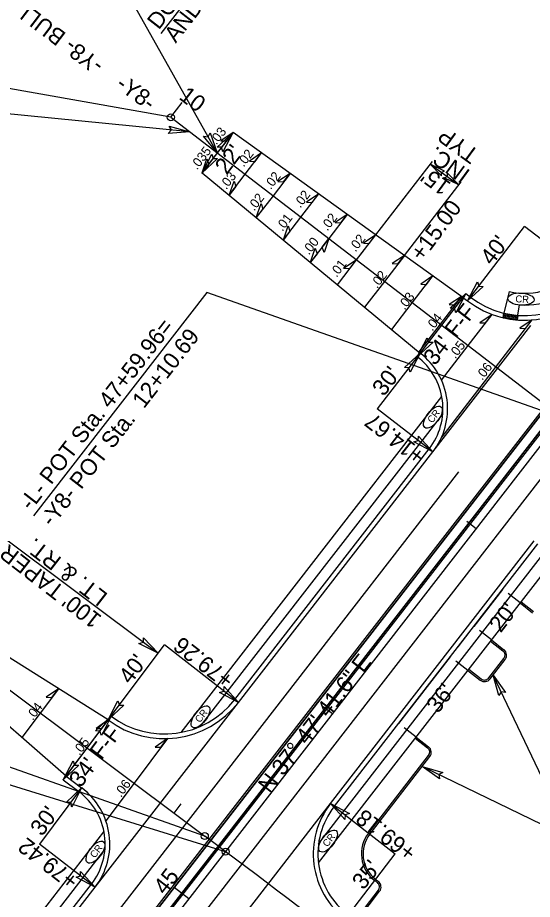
# Model space of a CAD drawing. Extents: x 2010838 to 2015151, y 441905 to 447792.
# Drawn here: x 2014378.8 to 2014598.5, y 445680 to 446056.5 of the extents above; entities that cross this region are included whole.
import ezdxf

# ---------------------------------------------------------------- set-up
doc = ezdxf.new("R2010")
doc.units = 0
for name, color, linetype in [('A-Wall-Blow', 7, 'Continuous'), ('A-Wall-Comp', 7, 'Continuous'), ('B-Border', 7, 'Continuous'), ('B-Sheet Number', 7, 'Continuous'), ('C-Building', 7, 'Continuous'), ('C-CURB STOPS', 7, 'Continuous'), ('C-EOP 1', 7, 'Continuous'), ('C-Grave Plots', 7, 'Continuous'), ('CLRD', 7, 'Continuous'), ('Cont-2-Lidar', 7, 'Continuous'), ('Default_10ft_LIDAR_Contou', 7, 'Continuous'), ('Default_2FT_LIDAR_Contour', 7, 'Continuous'), ('HATCH', 7, 'Continuous'), ('s-Existing Major', 7, 'Continuous'), ('S-Existing Minor', 7, 'Continuous'), ('S-overhead electric', 7, 'Continuous'), ('S-SITE LIGHT POLE REMOVE', 7, 'Continuous'), ('TEXT-LG', 7, 'Continuous'), ('TEXT-MED', 7, 'Continuous'), ('X2', 7, 'Continuous'), ('X4', 7, 'Continuous')]:
    doc.layers.add(name, color=color, linetype=linetype)

msp = doc.modelspace()

# ---------------------------------------------------------------- linework, layer by layer
at = {"layer": 'A-Wall-Blow'}
for p, q in [((2014470.79, 446007.47), (2014464.14, 445998.82)), ((2014464.19, 445998.88), (2014457.57, 445990.26)), ((2014475.94, 445989.56), (2014482.98, 445998.72)), ((2014469.13, 445980.69), (2014475.94, 445989.56)), ((2014495.17, 445989.96), (2014487.84, 445980.42)), ((2014499.73, 445971.28), (2014507.36, 445981.21)), ((2014487.84, 445980.42), (2014480.7, 445971.13)), ((2014492.26, 445961.56), (2014499.73, 445971.28)), ((2014519.56, 445972.46), (2014511.63, 445962.14)), ((2014511.63, 445962.14), (2014503.82, 445951.99)), ((2014523.52, 445953), (2014531.75, 445963.71)), ((2014543.94, 445954.96), (2014535.41, 445943.86)), ((2014515.39, 445942.42), (2014523.52, 445953)), ((2014535.41, 445943.86), (2014526.95, 445932.85)), ((2014547.31, 445934.72), (2014556.13, 445946.21)), ((2014568.33, 445937.46), (2014559.2, 445925.58)), ((2014538.51, 445923.28), (2014547.31, 445934.72)), ((2014571.1, 445916.44), (2014581.32, 445929.75)), ((2014559.2, 445925.58), (2014550.08, 445913.71)), ((2014559.6, 445876.86), (2014598.42, 445927.38)), ((2014559.76, 445901.69), (2014571.1, 445916.44)), ((2014396.27, 445769.9), (2014388.51, 445759.53)), ((2014388.51, 445759.53), (2014380.65, 445749.03)), ((2014408.53, 445744.55), (2014417.52, 445756.56)), ((2014442.78, 445748.6), (2014428.54, 445729.57)), ((2014399.54, 445732.54), (2014408.52, 445744.55)), ((2014428.54, 445729.57), (2014416.51, 445713.49))]:
    msp.add_line(p, q, dxfattribs=at)
at = {"layer": 'A-Wall-Comp'}
for points in [[(2014470.79, 446007.47), (2014465.55, 446003.93), (2014467.97, 446003.8)], [(2014457.57, 445990.26), (2014459.64, 445996.24), (2014460.39, 445993.93)], [(2014482.98, 445998.72), (2014477.74, 445995.18), (2014480.16, 445995.05)], [(2014495.17, 445989.96), (2014489.93, 445986.43), (2014492.35, 445986.3)], [(2014469.13, 445980.69), (2014471.2, 445986.67), (2014471.95, 445984.36)], [(2014507.36, 445981.21), (2014502.12, 445977.67), (2014504.55, 445977.55)], [(2014480.7, 445971.13), (2014482.77, 445977.1), (2014483.51, 445974.79)], [(2014519.56, 445972.46), (2014514.32, 445968.92), (2014516.74, 445968.79)], [(2014492.26, 445961.56), (2014494.33, 445967.53), (2014495.08, 445965.22)], [(2014511.63, 445962.14), (2014509.61, 445956.15), (2014508.84, 445958.45)], [(2014531.75, 445963.71), (2014526.51, 445960.17), (2014528.93, 445960.04)], [(2014503.82, 445951.99), (2014505.89, 445957.96), (2014506.64, 445955.65)], [(2014543.94, 445954.96), (2014538.7, 445951.42), (2014541.12, 445951.29)], [(2014523.52, 445953), (2014518.28, 445949.46), (2014520.7, 445949.33)], [(2014556.13, 445946.21), (2014550.89, 445942.67), (2014553.32, 445942.54)], [(2014568.33, 445937.46), (2014563.08, 445933.92), (2014565.51, 445933.79)], [(2014581.32, 445929.75), (2014576.08, 445926.21), (2014578.51, 445926.08)], [(2014598.42, 445927.38), (2014593.18, 445923.84), (2014595.6, 445923.71)], [(2014396.27, 445769.9), (2014391.08, 445766.3), (2014393.5, 445766.2)], [(2014417.52, 445756.56), (2014412.32, 445752.95), (2014414.75, 445752.85)], [(2014442.78, 445748.6), (2014437.59, 445745), (2014440.01, 445744.9)]]:
    msp.add_lwpolyline(points, close=True, dxfattribs=at)
at = {"layer": 'B-Border'}
for p, q in [((2014556.07, 445871.07), (2014597.9, 445924.99)), ((2014411.9, 445685.17), (2014473.09, 445764.07)), ((2014456.6, 445648.98), (2014512.35, 445720.86))]:
    msp.add_line(p, q, dxfattribs=at)
at = {"layer": 'B-Sheet Number'}
for p, q in [((2014593.33, 445806.52), (2014588.2, 445810.5)), ((2014581.08, 445790.71), (2014575.94, 445794.7)), ((2014570.99, 445777.7), (2014565.85, 445781.69)), ((2014548.92, 445749.26), (2014543.79, 445753.24))]:
    msp.add_line(p, q, dxfattribs=at)
at = {"layer": 'C-Building'}
for p, q in [((2014523.52, 445953), (2014526.57, 445956.97)), ((2014574.54, 445838.18), (2014570.59, 445841.24)), ((2014574.54, 445838.18), (2014570.59, 445841.24)), ((2014513.26, 445759.16), (2014509.31, 445762.22)), ((2014513.26, 445759.16), (2014509.31, 445762.22)), ((2014445.59, 445716.81), (2014448.59, 445720.81))]:
    msp.add_line(p, q, dxfattribs=at)
at = {"layer": 'C-CURB STOPS'}
for p, q in [((2014244.85, 445426.12), (2014703.05, 446016.93)), ((2014703.05, 446016.93), (2014244.85, 445426.12)), ((2014706.21, 446014.48), (2014313.99, 445508.74)), ((2014313.99, 445508.74), (2014706.21, 446014.48))]:
    msp.add_line(p, q, dxfattribs=at)
at = {"layer": 'C-EOP 1'}
for p, q in [((2014444.23, 446013.93), (2014449.1, 446020.28)), ((2014451.98, 445680.14), (2014445.65, 445685.04)), ((2014451.98, 445680.14), (2014445.65, 445685.04))]:
    msp.add_line(p, q, dxfattribs=at)
at = {"layer": 'CLRD'}
for p, q in [((2014251.18, 445421.22), (2014766.2, 446085.3)), ((2014251.18, 445421.22), (2014746.42, 446059.8)), ((2014444.23, 446013.93), (2014634.35, 445867.84)), ((2014444.23, 446013.93), (2014634.35, 445867.84)), ((2014285.47, 445836.64), (2014458.72, 445706.98)), ((2014285.47, 445836.64), (2014458.72, 445706.98))]:
    msp.add_line(p, q, dxfattribs=at)
msp.add_arc((2010378.3, 440254.75), 6810.04, 51.715108, 53.189015, dxfattribs=at)
msp.add_arc((2010378.3, 440254.75), 6810.04, 51.715108, 53.189015, dxfattribs=at)
at = {"layer": 'Default_10ft_LIDAR_Contou'}
for p, q in [((2014444.23, 446013.93), (2014338.92, 446032.54)), ((2014452.32, 446007.72), (2014343.9, 446018.46)), ((2014459.62, 445939.08), (2014385.65, 445843.7)), ((2014611.29, 445885.56), (2014459.62, 445939.08)), ((2014458.72, 445706.98), (2014332.35, 445751.6)), ((2014467.62, 445700.31), (2014337.54, 445740.52))]:
    msp.add_line(p, q, dxfattribs=at)
for centre in [(2014444.23, 446013.93), (2014458.72, 445706.98), (2014467.62, 445700.31)]:
    msp.add_circle(centre, 1.5, dxfattribs=at)
at = {"layer": 'HATCH'}
for p, q in [((2014463.45, 445709.2), (2014731.87, 446055.32)), ((2014507.92, 445737.99), (2014751.83, 446052.49)), ((2014467.79, 445705.83), (2014736.21, 446051.95)), ((2014234.78, 445433.94), (2014567.14, 445862.49)), ((2014446.63, 445658.97), (2014507.92, 445737.99)), ((2014432.8, 445669.69), (2014463.45, 445709.2)), ((2014437.15, 445666.32), (2014467.79, 445705.83))]:
    msp.add_line(p, q, dxfattribs=at)
at = {"layer": 's-Existing Major'}
for points in [[(2014443.51, 446010.15), (2014452.32, 446007.72), (2014443.15, 446007.02), (2014444.46, 446008.5)], [(2014460.99, 446007.3), (2014464.05, 445998.7), (2014458.22, 446005.8), (2014460.18, 446005.59)], [(2014463.99, 446001.16), (2014470.7, 446007.35), (2014466.45, 445999.2), (2014465.88, 446001.09)], [(2014464.14, 445996.28), (2014457.43, 445990.09), (2014461.68, 445998.24), (2014462.24, 445996.35)], [(2014561.11, 445990.9), (2014554.97, 445993.92), (2014559.75, 445988.96), (2014559.76, 445990.44)], [(2014562.33, 445990.01), (2014567.1, 445985.1), (2014560.91, 445988.12), (2014562.31, 445988.59)], [(2014577.58, 445941.73), (2014570.86, 445935.54), (2014575.11, 445943.69), (2014575.68, 445941.8)], [(2014563.43, 445932.42), (2014570.14, 445938.61), (2014565.9, 445930.46), (2014565.33, 445932.35)], [(2014556.14, 445917.84), (2014549.43, 445911.65), (2014553.67, 445919.8), (2014554.24, 445917.92)], [(2014543.93, 445907.05), (2014550.65, 445913.24), (2014546.4, 445905.09), (2014545.83, 445906.97)], [(2014549.91, 445877.81), (2014556.07, 445871.07), (2014547.94, 445875.35), (2014549.83, 445875.91)], [(2014432.56, 445791.67), (2014438.83, 445785.04), (2014430.63, 445789.18), (2014432.51, 445789.77)], [(2014584.27, 445766.95), (2014581.81, 445775.75), (2014587.14, 445768.26), (2014585.2, 445768.61)], [(2014466.93, 445770.81), (2014473.09, 445764.07), (2014464.96, 445768.35), (2014466.85, 445768.91)], [(2014424.15, 445762.83), (2014417.52, 445756.56), (2014421.66, 445764.76), (2014422.25, 445762.88)], [(2014412.08, 445751.88), (2014418.71, 445758.16), (2014414.57, 445749.95), (2014413.98, 445751.83)], [(2014404.98, 445737.21), (2014398.34, 445730.94), (2014402.48, 445739.14), (2014403.08, 445737.26)], [(2014558.94, 445731.38), (2014551.53, 445736.7), (2014560.37, 445734.19), (2014558.63, 445733.25)], [(2014399.54, 445721.3), (2014406.17, 445727.57), (2014402.03, 445719.37), (2014401.44, 445721.25)], [(2014518.51, 445714.12), (2014512.35, 445720.86), (2014520.48, 445716.58), (2014518.59, 445716.02)], [(2014405.74, 445691.91), (2014411.9, 445685.17), (2014403.77, 445689.45), (2014405.66, 445690.01)]]:
    msp.add_lwpolyline(points, close=True, dxfattribs=at)
at = {"layer": 'S-Existing Minor'}
for p, q in [((2014440.14, 446049.74), (2014544.06, 446183.74)), ((2014464.05, 445998.7), (2014404.61, 446104.4)), ((2014457.57, 445990.26), (2014470.79, 446007.47)), ((2014554.97, 445993.92), (2014567.1, 445985.1)), ((2014570.86, 445935.54), (2014595.24, 445967.25)), ((2014626.85, 445942.74), (2014595.24, 445967.25)), ((2014570.14, 445938.61), (2014549.43, 445911.65)), ((2014550.65, 445913.24), (2014532.37, 445889.45)), ((2014556.07, 445871.07), (2014532.37, 445889.45)), ((2014358.77, 445844.96), (2014438.83, 445785.04)), ((2014417.52, 445756.56), (2014441.48, 445788.58)), ((2014473.09, 445764.07), (2014441.48, 445788.58)), ((2014615.04, 445705.84), (2014581.81, 445775.75)), ((2014398.34, 445730.94), (2014418.71, 445758.16)), ((2014615.04, 445705.84), (2014551.53, 445736.7)), ((2014406.17, 445727.57), (2014388.2, 445703.56)), ((2014512.35, 445720.86), (2014540.01, 445699.41)), ((2014411.9, 445685.17), (2014388.2, 445703.56)), ((2014518.75, 445671.61), (2014540.01, 445699.41))]:
    msp.add_line(p, q, dxfattribs=at)
for points in [[(2014531.75, 445963.71), (2014555.85, 445995.07)], [(2014543.94, 445954.96), (2014568.1, 445986.4)]]:
    msp.add_lwpolyline(points, dxfattribs=at)
at = {"layer": 'S-overhead electric'}
for p, q in [((2014568.93, 445937.03), (2014470.79, 446007.47)), ((2014457.57, 445990.26), (2014550.65, 445913.24)), ((2014568.93, 445937.03), (2014570.86, 445935.54)), ((2014473.09, 445764.07), (2014556.07, 445871.07)), ((2014512.35, 445720.86), (2014599.34, 445833.03)), ((2014417.52, 445756.56), (2014332.56, 445809.93)), ((2014399.54, 445732.54), (2014323.99, 445798.49)), ((2014399.54, 445732.54), (2014406.17, 445727.57)), ((2014336.06, 445587.37), (2014411.9, 445685.17))]:
    msp.add_line(p, q, dxfattribs=at)
for centre, radius, start, end in [((2014595.24, 445967.25), 40, 232.4598, 322.2051), ((2014532.37, 445889.45), 30, 322.2051, 52.4598), ((2014441.48, 445788.58), 40, 233.189, 322.2051), ((2014388.2, 445703.56), 30, 322.2051, 53.189), ((2014540.01, 445699.41), 35, 142.2051, 232.607)]:
    msp.add_arc(centre, radius, start, end, dxfattribs=at)
at = {"layer": 'S-SITE LIGHT POLE REMOVE'}
for p, q in [((2014593.33, 445806.52), (2014598.67, 445802.38)), ((2014593.74, 445807.05), (2014599.08, 445802.91)), ((2014580.67, 445790.19), (2014586, 445786.05)), ((2014581.08, 445790.71), (2014586.41, 445786.58)), ((2014580, 445774.51), (2014586.41, 445782.78)), ((2014580.53, 445774.1), (2014586.94, 445782.37)), ((2014570.99, 445777.7), (2014576.32, 445773.57)), ((2014571.4, 445778.23), (2014576.73, 445774.1)), ((2014548.51, 445748.73), (2014553.85, 445744.59)), ((2014548.92, 445749.26), (2014554.26, 445745.12)), ((2014528.74, 445708.41), (2014554.26, 445741.32)), ((2014529.26, 445708), (2014554.79, 445740.91)), ((2014522.93, 445670.93), (2014532.81, 445683.83)), ((2014523.46, 445670.52), (2014533.34, 445683.43))]:
    msp.add_line(p, q, dxfattribs=at)
for centre, radius, start, end in [((2014584.57, 445784.21), 2.33, 322.2051, 52.2051), ((2014584.57, 445784.21), 3, 322.2051, 52.2051), ((2014578.16, 445775.94), 3, 232.2051, 322.2051), ((2014578.16, 445775.94), 2.33, 232.2051, 322.2051), ((2014552.42, 445742.75), 2.33, 322.2051, 52.2051), ((2014552.42, 445742.75), 3, 322.2051, 52.2051), ((2014540.01, 445699.41), 14.42, 142.2051, 232.607), ((2014540.01, 445699.41), 13.75, 142.2051, 232.607), ((2010378.3, 440254.75), 6838.62, 52.595176, 52.606991), ((2010378.3, 440254.75), 6839.29, 52.595176, 52.606991), ((2014530.96, 445685.25), 2.33, 322.57, 52.5952), ((2014530.96, 445685.25), 3, 322.57, 52.5952)]:
    msp.add_arc(centre, radius, start, end, dxfattribs=at)
at = {"layer": 'TEXT-LG'}
for p, q in [((2014588.62, 445939.53), (2014586.41, 445930.29)), ((2014592.34, 445929.37), (2014593.05, 445933.83)), ((2014586.09, 445928.32), (2014586.41, 445930.29)), ((2014586.09, 445928.32), (2014592.02, 445927.37)), ((2014586.41, 445930.29), (2014592.33, 445929.34)), ((2014592.33, 445929.34), (2014592.02, 445927.37)), ((2014448.6, 445751.25), (2014559.87, 445894.72)), ((2014456.96, 445753.88), (2014560.27, 445887.08)), ((2014507.29, 445703.73), (2014604.47, 445829.04)), ((2014507.24, 445695.51), (2014608.42, 445825.98)), ((2014311.57, 445574.56), (2014415.7, 445708.83)), ((2014319.93, 445577.18), (2014416.1, 445701.18))]:
    msp.add_line(p, q, dxfattribs=at)
for centre in [(2014586.52, 445928.51), (2014586.6, 445929.06), (2014586.67, 445929.51), (2014586.73, 445929.94), (2014587.08, 445928.42), (2014587.16, 445928.97), (2014587.24, 445929.42), (2014587.3, 445929.85), (2014587.67, 445928.32), (2014587.75, 445928.87), (2014587.83, 445929.32), (2014587.89, 445929.75), (2014588.24, 445928.23), (2014588.32, 445928.78), (2014588.4, 445929.23), (2014588.46, 445929.66), (2014588.83, 445928.13), (2014588.91, 445928.68), (2014588.99, 445929.13), (2014589.05, 445929.56), (2014589.43, 445928.04), (2014589.51, 445928.59), (2014589.59, 445929.04), (2014589.65, 445929.47), (2014590.03, 445927.94), (2014590.11, 445928.49), (2014590.19, 445928.94), (2014590.24, 445929.37), (2014590.67, 445928.4), (2014590.75, 445928.85), (2014590.81, 445929.28), (2014591.26, 445928.3), (2014591.34, 445928.75), (2014591.4, 445929.18), (2014591.83, 445928.21), (2014591.91, 445928.66), (2014591.97, 445929.09), (2014590.59, 445927.85), (2014591.19, 445927.75), (2014591.75, 445927.66)]:
    msp.add_circle(centre, 0.0869, dxfattribs=at)
for radius, start in [(28.5, 256.5671), (33.5, 266.2614)]:
    msp.add_arc((2014595.24, 445967.25), radius, start, 322.2051, dxfattribs=at)
at = {"layer": 'TEXT-MED'}
for p, q in [((2014570.14, 445938.61), (2014572.08, 445937.12)), ((2014471.51, 445765.29), (2014554.49, 445872.29)), ((2014514.05, 445719.79), (2014600.92, 445831.8)), ((2014566.84, 445787.86), (2014571.97, 445794.48)), ((2014398.34, 445730.94), (2014404.97, 445725.97)), ((2014334.48, 445588.6), (2014410.32, 445686.4))]:
    msp.add_line(p, q, dxfattribs=at)
for centre, radius, start, end in [((2014595.24, 445967.25), 38, 232.4598, 322.2051), ((2014532.37, 445889.45), 28, 322.2051, 52.4598), ((2014441.48, 445788.58), 38, 233.189, 322.2051), ((2014388.2, 445703.56), 28, 322.2051, 53.189), ((2014540.01, 445699.41), 33, 142.2051, 232.607)]:
    msp.add_arc(centre, radius, start, end, dxfattribs=at)
at = {"layer": 'X2'}
for p, q in [((2014585.83, 445812.34), (2014573.57, 445796.54)), ((2014563.48, 445783.53), (2014541.42, 445755.08))]:
    msp.add_line(p, q, dxfattribs=at)
at = {"layer": 'X4'}
for centre, major_axis in [((2014593.67, 445936.29), (5.6, -0.33)), ((2014556.09, 445885.84), (3.43, 4.44)), ((2014456.89, 445757.9), (3.43, 4.44)), ((2014511.33, 445704.86), (3.43, 4.44)), ((2014412.05, 445700.09), (3.43, 4.44))]:
    msp.add_ellipse(centre, major_axis=major_axis, ratio=0.462467, dxfattribs=at)

# ---------------------------------------------------------------- texts
at = {"layer": 'A-Wall-Blow'}
for s, rotation, p in [('.03', 52.4598, (2014463.67, 446001.87)), ('.035', 52.4598, (2014455.42, 445991.19)), ('.02', 52.4598, (2014475.32, 445992.42)), ('.03', 52.4598, (2014467.89, 445982.8)), ('.02', 52.4598, (2014486.87, 445982.82)), ('.02', 52.4598, (2014479.84, 445973.62)), ('.02', 52.4598, (2014499.51, 445974.91)), ('.01', 52.4598, (2014491.87, 445964.97)), ('.02', 52.4598, (2014511.05, 445965.13)), ('.00', 52.4598, (2014503.17, 445954.83)), ('.02', 52.4598, (2014523.04, 445956.15)), ('.01', 52.4598, (2014514.98, 445945.33)), ('.02', 52.4598, (2014532.28, 445940.6)), ('.03', 52.4598, (2014544.03, 445931.36)), ('.04', 52.4598, (2014555.83, 445922.34)), ('.05', 52.4598, (2014565.67, 445910.58)), ('.06', 52.4598, (2014577.17, 445901.33)), ('.04', 53.189, (2014385.33, 445756.14)), ('.05', 53.189, (2014405.29, 445741.17)), ('.06', 53.189, (2014422.96, 445723.25))]:
    msp.add_text(s, height=4, rotation=rotation, dxfattribs=at).set_placement(p)
at = {"layer": 'C-Grave Plots'}
for s, rotation, p in [('DO NOT DISTURB RETAINING WALL', 52.1339, (2014439.09, 446050.96)), ('AND WROUGHT IRON FENCE', 52.1339, (2014446.34, 446045.33)), ('-Y8- BULLARD ST.', 142.7607, (2014416.08, 446037.27)), ('TYP', 143.9055, (2014576.31, 445999.34)), ("22'", 53.189, (2014468.08, 445989.09)), ('INC. ', 143.9055, (2014572.48, 445990.87)), ("15'", 143.9055, (2014564.23, 445985.62)), ('+15.00', 53.579, (2014551.52, 445952.03)), ("40'", 52.7401, (2014581.32, 445950.3)), ("34' F-F", 52.4598, (2014556.97, 445907.52)), ("30'", 52.3089, (2014535.13, 445894.39)), ('+14.67', 142.2051, (2014553.44, 445870.52)), ('LT. & RT.', 142.2051, (2014417.76, 445810.14)), ("100' TAPER", 142.2051, (2014415.18, 445800.62)), ("20'", 52.2609, (2014585.01, 445793.45)), ('+79.26', 142.2051, (2014471.77, 445774.86)), ("40'", 53.189, (2014426.99, 445771.43)), ("36'", 52.2609, (2014558.22, 445758.99)), ("34' F-F", 53.189, (2014405.82, 445727.33)), ("30'", 53.4616, (2014389.27, 445706.53)), ('+69.18', 142.2051, (2014549.62, 445701.18)), ('+79.42', 142.2051, (2014405.47, 445689.06)), ("35'", 51.1993, (2014526.45, 445683.65))]:
    msp.add_text(s, height=7, rotation=rotation, dxfattribs=at).set_placement(p)
at = {"layer": 'Cont-2-Lidar'}
msp.add_text('N 37%%d 47\' 41.6" E', height=7, rotation=52.2051, dxfattribs=at).set_placement((2014486.44, 445724.91))
at = {"layer": 'Default_10ft_LIDAR_Contou'}
for s, p in [('-L- POT Sta. 47+59.96=', (2014384.53, 445845.6)), ('-Y8- POT Sta.  12+10.69', (2014393.52, 445838.63))]:
    msp.add_text(s, height=7, rotation=52.2051, dxfattribs=at).set_placement(p)
at = {"layer": 'Default_2FT_LIDAR_Contour'}
for s, rotation, p in [('-Y8-', 323.8133, (2014420.35, 446026.89)), ('10', 322.4598, (2014447.31, 446022.03)), ('45', 52.2051, (2014441.77, 445681.49))]:
    msp.add_text(s, height=7, rotation=rotation, dxfattribs=at).set_placement(p)
at = {"layer": 'X4'}
for rotation, p in [(356.5804, (2014591.23, 445934.95)), (52.2869, (2014555.81, 445883.07)), (52.2869, (2014456.62, 445755.13)), (52.2869, (2014511.06, 445702.09)), (52.2869, (2014411.78, 445697.32))]:
    msp.add_text('CR', height=3, rotation=rotation, dxfattribs=at).set_placement(p)

doc.saveas('drawing.dxf')
